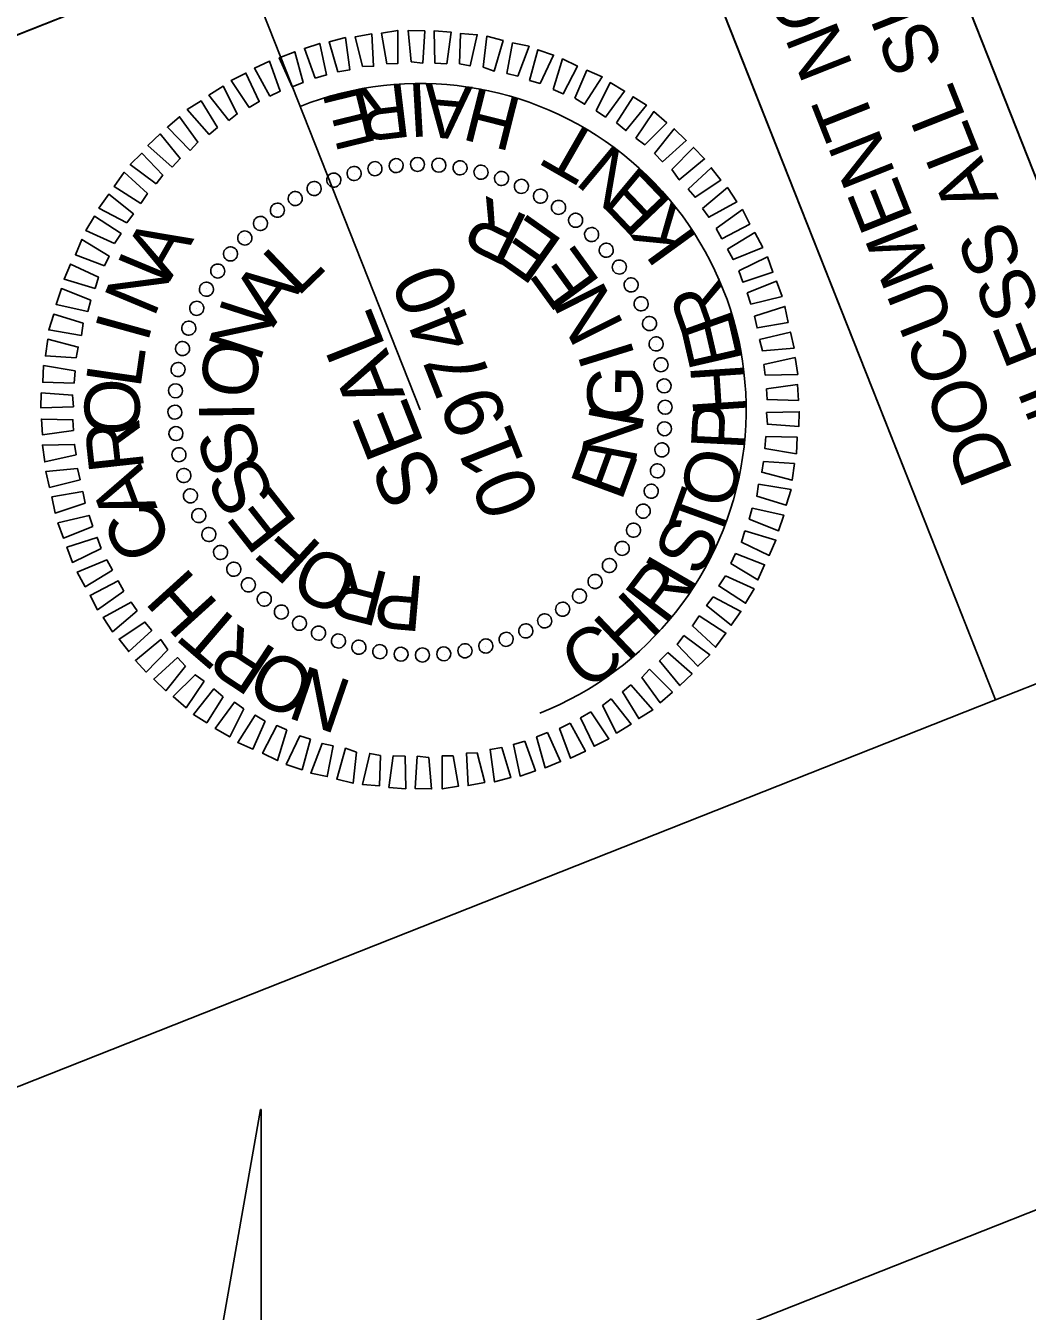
# Model space of a CAD drawing. Extents: x 1250120 to 1251758, y 748130 to 750098.
# Drawn here: x 1250261.4 to 1250363.9, y 749494.4 to 749625.9 of the extents above; entities that cross this region are included whole.
import ezdxf

# ---------------------------------------------------------------- set-up
doc = ezdxf.new("R2010")
doc.units = 0
for name, color, linetype in [('Prop North Arrow for Plan Sheets CELL', 7, 'Continuous'), ('Scratch_Level_0', 7, 'Continuous'), ('Scratch_Level_1', 7, 'Continuous'), ('Sheet Layout Plan Border', 7, 'Continuous'), ('Sheet Plan And Profile CELL', 7, 'Continuous'), ('Sheet Professional Seal CELL', 7, 'Continuous'), ('Sheet Sticker Exception Certification CELL', 7, 'Continuous')]:
    doc.layers.add(name, color=color, linetype=linetype)

msp = doc.modelspace()

# ---------------------------------------------------------------- linework, layer by layer
at = {"layer": 'Prop North Arrow for Plan Sheets CELL'}
for p, q in [((1250277.24, 749468.71), (1250285.44, 749515.06)), ((1250285.49, 749515.06), (1250285.44, 749515.06)), ((1250285.49, 749515.06), (1250285.44, 749515.06)), ((1250285.49, 749515.06), (1250285.49, 749467.26))]:
    msp.add_line(p, q, dxfattribs=at)
at = {"layer": 'Scratch_Level_0'}
msp.add_lwpolyline([(1250308.89, 749751.61), (1250344.17, 749765.56), (1250417.72, 749579.54), (1250382.44, 749565.59)], close=True, dxfattribs=at)
msp.add_arc((1250301.74, 749586.63), 33.36, 291.5743, 111.5743, dxfattribs=at)
at = {"layer": 'Scratch_Level_1'}
for q in [(1250206.96, 749826.33), (1250301.74, 749586.63)]:
    msp.add_line((1250301.74, 749586.63), q, dxfattribs=at)
at = {"layer": 'Sheet Layout Plan Border'}
msp.add_lwpolyline([(1251145.64, 748523.25), (1250727.17, 748357.78), (1250285.93, 749473.66), (1250436.11, 749533.04), (1250362.55, 749719.08), (1250630.85, 749825.16)], close=True, dxfattribs=at)
at = {"layer": 'Sheet Plan And Profile CELL'}
msp.add_line((1250219.18, 749608.62), (1250323.75, 749649.97), dxfattribs=at)
for points in [[(1250219.18, 749608.62), (1250182.41, 749701.61), (1250287.03, 749742.98), (1250323.8, 749649.99)], [(1250255.97, 749515.58), (1250219.18, 749608.62), (1250323.8, 749649.99), (1250360.59, 749556.95)]]:
    msp.add_lwpolyline(points, close=True, dxfattribs=at)
at = {"layer": 'Sheet Professional Seal CELL'}
for p, q in [((1250297.15, 749611.27), (1250297.15, 749611.27)), ((1250299.27, 749611.63), (1250299.27, 749611.63)), ((1250301.48, 749611.75), (1250301.48, 749611.75)), ((1250303.67, 749611.65), (1250303.67, 749611.65)), ((1250305.85, 749611.43), (1250305.85, 749611.43)), ((1250292.92, 749610.14), (1250292.92, 749610.14)), ((1250295.03, 749610.81), (1250295.03, 749610.81)), ((1250307.99, 749610.93), (1250307.99, 749610.93)), ((1250310.11, 749610.32), (1250310.11, 749610.32)), ((1250290.9, 749609.28), (1250290.9, 749609.28)), ((1250312.1, 749609.49), (1250312.1, 749609.49)), ((1250314.11, 749608.51), (1250314.11, 749608.51)), ((1250289.01, 749608.21), (1250289.01, 749608.21)), ((1250315.91, 749607.34), (1250315.91, 749607.34)), ((1250287.11, 749607.03), (1250287.11, 749607.03)), ((1250317.68, 749606), (1250317.68, 749606)), ((1250285.38, 749605.7), (1250285.38, 749605.7)), ((1250319.33, 749604.55), (1250319.33, 749604.55)), ((1250283.81, 749604.22), (1250283.81, 749604.22)), ((1250282.37, 749602.57), (1250282.37, 749602.57)), ((1250320.81, 749602.99), (1250320.81, 749602.99)), ((1250281.02, 749600.81), (1250281.02, 749600.81)), ((1250322.14, 749601.26), (1250322.14, 749601.26)), ((1250323.32, 749599.36), (1250323.32, 749599.36)), ((1250279.85, 749599), (1250279.85, 749599)), ((1250278.87, 749597), (1250278.87, 749597)), ((1250324.39, 749597.47), (1250324.39, 749597.47)), ((1250325.24, 749595.44), (1250325.24, 749595.44)), ((1250278.05, 749595.01), (1250278.05, 749595.01)), ((1250277.43, 749592.88), (1250277.43, 749592.88)), ((1250325.91, 749593.34), (1250325.91, 749593.34)), ((1250276.93, 749590.75), (1250276.93, 749590.75)), ((1250326.38, 749591.21), (1250326.38, 749591.21)), ((1250326.73, 749589.09), (1250326.73, 749589.09)), ((1250276.72, 749588.57), (1250276.72, 749588.57)), ((1250276.62, 749586.38), (1250276.62, 749586.38)), ((1250301.74, 749586.63), (1250301.74, 749586.63)), ((1250326.85, 749586.88), (1250326.85, 749586.88)), ((1250276.74, 749584.17), (1250276.74, 749584.17)), ((1250326.75, 749584.69), (1250326.75, 749584.69)), ((1250326.54, 749582.51), (1250326.54, 749582.51)), ((1250277.09, 749582.05), (1250277.09, 749582.05)), ((1250277.56, 749579.92), (1250277.56, 749579.92)), ((1250326.04, 749580.38), (1250326.04, 749580.38)), ((1250325.43, 749578.25), (1250325.43, 749578.25)), ((1250278.23, 749577.82), (1250278.23, 749577.82)), ((1250279.08, 749575.79), (1250279.08, 749575.79)), ((1250324.6, 749576.26), (1250324.6, 749576.26)), ((1250323.62, 749574.26), (1250323.62, 749574.26)), ((1250280.15, 749573.9), (1250280.15, 749573.9)), ((1250281.33, 749572), (1250281.33, 749572)), ((1250322.45, 749572.45), (1250322.45, 749572.45)), ((1250282.66, 749570.27), (1250282.66, 749570.27)), ((1250321.11, 749570.69), (1250321.11, 749570.69)), ((1250319.66, 749569.04), (1250319.66, 749569.04)), ((1250284.14, 749568.71), (1250284.14, 749568.71)), ((1250285.79, 749567.26), (1250285.79, 749567.26)), ((1250318.09, 749567.56), (1250318.09, 749567.56)), ((1250287.56, 749565.92), (1250287.56, 749565.92)), ((1250314.46, 749565.05), (1250314.46, 749565.05)), ((1250316.36, 749566.23), (1250316.36, 749566.23)), ((1250289.37, 749564.75), (1250289.37, 749564.75)), ((1250291.37, 749563.77), (1250291.37, 749563.77)), ((1250312.57, 749563.98), (1250312.57, 749563.98)), ((1250293.36, 749562.94), (1250293.36, 749562.94)), ((1250308.45, 749562.45), (1250308.45, 749562.45)), ((1250310.55, 749563.12), (1250310.55, 749563.12)), ((1250295.48, 749562.33), (1250295.48, 749562.33)), ((1250297.62, 749561.83), (1250297.62, 749561.83)), ((1250299.8, 749561.62), (1250299.8, 749561.62)), ((1250301.99, 749561.51), (1250301.99, 749561.51)), ((1250304.2, 749561.63), (1250304.2, 749561.63)), ((1250306.32, 749561.99), (1250306.32, 749561.99))]:
    msp.add_line(p, q, dxfattribs=at)
for points in [[(1250293.35, 749621.17), (1250292.45, 749624.25), (1250294.11, 749624.69), (1250294.56, 749621.37)], [(1250295.87, 749621.73), (1250295.1, 749624.76), (1250296.81, 749625.06), (1250296.99, 749621.75)], [(1250298.34, 749622.01), (1250297.8, 749625.13), (1250299.47, 749625.41), (1250299.46, 749622.02)], [(1250300.85, 749622.19), (1250300.54, 749625.41), (1250302.22, 749625.37), (1250302.02, 749622.07)], [(1250303.26, 749622.07), (1250303.19, 749625.38), (1250304.91, 749625.25), (1250304.47, 749622.01)], [(1250305.77, 749621.99), (1250305.88, 749625.1), (1250307.6, 749624.97), (1250306.87, 749621.78)], [(1250308.21, 749621.66), (1250308.57, 749624.82), (1250310.24, 749624.4), (1250309.34, 749621.25)], [(1250310.62, 749621), (1250311.21, 749624.14), (1250312.9, 749623.79), (1250311.74, 749620.75)], [(1250288.68, 749619.64), (1250287.35, 749622.61), (1250288.93, 749623.24), (1250289.8, 749620.08)], [(1250291.03, 749620.52), (1250289.92, 749623.57), (1250291.49, 749624.09), (1250292.18, 749620.86)], [(1250312.94, 749620.31), (1250313.79, 749623.44), (1250315.41, 749622.9), (1250314.03, 749619.99)], [(1250286.38, 749618.68), (1250284.81, 749621.55), (1250286.35, 749622.27), (1250287.45, 749619.21)], [(1250315.35, 749619.38), (1250316.32, 749622.5), (1250317.84, 749621.77), (1250316.39, 749618.93)], [(1250284.25, 749617.52), (1250282.41, 749620.28), (1250283.93, 749621.05), (1250285.3, 749618.14)], [(1250317.58, 749618.49), (1250318.82, 749621.34), (1250320.38, 749620.67), (1250318.58, 749617.86)], [(1250282.19, 749616.21), (1250280.15, 749618.79), (1250281.62, 749619.7), (1250283.05, 749616.88)], [(1250319.76, 749617.2), (1250321.2, 749620.08), (1250322.67, 749619.21), (1250320.71, 749616.55)], [(1250280.18, 749614.77), (1250277.93, 749617.33), (1250279.35, 749618.21), (1250281.02, 749615.49)], [(1250321.85, 749615.98), (1250323.54, 749618.64), (1250324.9, 749617.78), (1250322.81, 749615.18)], [(1250278.24, 749613.15), (1250275.91, 749615.51), (1250277.15, 749616.59), (1250279.03, 749614)], [(1250323.82, 749614.4), (1250325.65, 749617.11), (1250326.97, 749615.96), (1250324.73, 749613.73)], [(1250325.73, 749612.84), (1250327.74, 749615.36), (1250328.97, 749614.17), (1250326.55, 749611.98)], [(1250276.38, 749611.45), (1250273.9, 749613.64), (1250275.15, 749614.83), (1250277.22, 749612.32)], [(1250274.75, 749609.73), (1250272.1, 749611.69), (1250273.3, 749612.86), (1250275.42, 749610.63)], [(1250327.51, 749611.18), (1250329.73, 749613.45), (1250330.84, 749612.28), (1250328.25, 749610.13)], [(1250329.16, 749609.19), (1250331.53, 749611.37), (1250332.51, 749610.09), (1250329.87, 749608.35)], [(1250273.18, 749607.71), (1250270.44, 749609.47), (1250271.49, 749610.91), (1250273.86, 749608.73)], [(1250271.76, 749605.75), (1250268.9, 749607.25), (1250269.9, 749608.67), (1250272.42, 749606.65)], [(1250330.65, 749607.2), (1250333.19, 749609.34), (1250334.14, 749607.88), (1250331.27, 749606.32)], [(1250332.04, 749605.17), (1250334.72, 749607.09), (1250335.47, 749605.61), (1250332.62, 749604.11)], [(1250270.49, 749603.63), (1250267.56, 749604.95), (1250268.43, 749606.42), (1250271.17, 749604.65)], [(1250333.2, 749603.05), (1250335.98, 749604.74), (1250336.79, 749603.23), (1250333.78, 749601.99)], [(1250269.46, 749601.34), (1250266.49, 749602.48), (1250267.16, 749604.04), (1250269.93, 749602.34)], [(1250334.35, 749600.82), (1250337.28, 749602.25), (1250337.84, 749600.69), (1250334.75, 749599.68)], [(1250268.5, 749599.03), (1250265.33, 749599.98), (1250266, 749601.53), (1250268.85, 749600.19)], [(1250335.19, 749598.57), (1250338.21, 749599.76), (1250338.77, 749598.21), (1250335.58, 749597.43)], [(1250267.76, 749596.69), (1250264.52, 749597.4), (1250265.06, 749599.01), (1250268.06, 749597.83)], [(1250335.97, 749596.19), (1250339.07, 749597.2), (1250339.39, 749595.55), (1250336.22, 749595)], [(1250267.11, 749594.23), (1250263.77, 749594.79), (1250264.27, 749596.39), (1250267.27, 749595.48)], [(1250336.48, 749593.81), (1250339.62, 749594.57), (1250340, 749592.94), (1250336.78, 749592.64)], [(1250266.58, 749591.92), (1250263.43, 749592.13), (1250263.67, 749593.84), (1250266.78, 749593.03)], [(1250336.91, 749591.24), (1250340.11, 749591.97), (1250340.37, 749590.24), (1250337.06, 749590.17)], [(1250266.35, 749589.36), (1250263.15, 749589.44), (1250263.23, 749591.14), (1250266.46, 749590.59)], [(1250337.18, 749588.76), (1250340.34, 749589.21), (1250340.45, 749587.58), (1250337.24, 749587.66)], [(1250266.3, 749586.92), (1250262.94, 749586.83), (1250262.99, 749588.35), (1250266.2, 749588.12)], [(1250337.17, 749586.34), (1250340.53, 749586.43), (1250340.48, 749584.91), (1250337.27, 749585.14)], [(1250266.29, 749584.5), (1250263.13, 749584.05), (1250263.02, 749585.68), (1250266.23, 749585.6)], [(1250337.12, 749583.9), (1250340.32, 749583.82), (1250340.24, 749582.12), (1250337.01, 749582.67)], [(1250266.56, 749582.02), (1250263.36, 749581.29), (1250263.11, 749583.02), (1250266.41, 749583.09)], [(1250336.89, 749581.34), (1250340.04, 749581.13), (1250339.8, 749579.42), (1250336.69, 749580.23)], [(1250266.99, 749579.45), (1250263.85, 749578.69), (1250263.48, 749580.32), (1250266.69, 749580.62)], [(1250267.5, 749577.07), (1250264.41, 749576.06), (1250264.08, 749577.71), (1250267.25, 749578.26)], [(1250336.36, 749579.03), (1250339.7, 749578.47), (1250339.2, 749576.87), (1250336.2, 749577.78)], [(1250268.28, 749574.69), (1250265.26, 749573.5), (1250264.7, 749575.05), (1250267.89, 749575.83)], [(1250335.72, 749576.57), (1250338.95, 749575.86), (1250338.41, 749574.25), (1250335.41, 749575.43)], [(1250334.97, 749574.23), (1250338.14, 749573.28), (1250337.47, 749571.73), (1250334.62, 749573.07)], [(1250269.12, 749572.44), (1250266.19, 749571.01), (1250265.63, 749572.57), (1250268.72, 749573.58)], [(1250334.01, 749571.92), (1250336.98, 749570.78), (1250336.31, 749569.22), (1250333.54, 749570.92)], [(1250270.27, 749570.21), (1250267.5, 749568.52), (1250266.68, 749570.03), (1250269.69, 749571.27)], [(1250271.43, 749568.09), (1250268.75, 749566.17), (1250268, 749567.65), (1250270.85, 749569.15)], [(1250332.98, 749569.63), (1250335.91, 749568.31), (1250335.05, 749566.84), (1250332.3, 749568.61)], [(1250272.82, 749566.06), (1250270.28, 749563.92), (1250269.33, 749565.38), (1250272.21, 749566.94)], [(1250331.71, 749567.51), (1250334.57, 749566.01), (1250333.57, 749564.59), (1250331.05, 749566.61)], [(1250330.29, 749565.55), (1250333.03, 749563.79), (1250331.98, 749562.35), (1250329.61, 749564.53)], [(1250274.31, 749564.07), (1250271.94, 749561.89), (1250270.96, 749563.17), (1250273.6, 749564.91)], [(1250275.96, 749562.08), (1250273.74, 749559.81), (1250272.63, 749560.98), (1250275.22, 749563.13)], [(1250328.72, 749563.53), (1250331.38, 749561.57), (1250330.17, 749560.4), (1250328.06, 749562.63)], [(1250277.74, 749560.42), (1250275.73, 749557.9), (1250274.51, 749559.09), (1250276.92, 749561.28)], [(1250327.09, 749561.81), (1250329.57, 749559.62), (1250328.32, 749558.43), (1250326.25, 749560.94)], [(1250325.23, 749560.11), (1250327.56, 749557.75), (1250326.32, 749556.67), (1250324.44, 749559.26)], [(1250279.65, 749558.86), (1250277.82, 749556.15), (1250276.5, 749557.3), (1250278.74, 749559.53)], [(1250323.29, 749558.49), (1250325.54, 749555.93), (1250324.12, 749555.05), (1250322.45, 749557.77)], [(1250281.62, 749557.28), (1250279.93, 749554.62), (1250278.57, 749555.48), (1250280.66, 749558.08)], [(1250283.71, 749556.06), (1250282.27, 749553.18), (1250280.8, 749554.05), (1250282.76, 749556.71)], [(1250321.28, 749557.05), (1250323.33, 749554.47), (1250321.85, 749553.56), (1250320.42, 749556.38)], [(1250285.89, 749554.77), (1250284.65, 749551.92), (1250283.1, 749552.59), (1250284.89, 749555.4)], [(1250317.1, 749554.58), (1250318.66, 749551.71), (1250317.12, 749550.99), (1250316.02, 749554.05)], [(1250319.22, 749555.74), (1250321.06, 749552.98), (1250319.54, 749552.21), (1250318.17, 749555.12)], [(1250288.12, 749553.88), (1250287.16, 749550.76), (1250285.63, 749551.5), (1250287.09, 749554.33)], [(1250290.53, 749552.95), (1250289.68, 749549.82), (1250288.06, 749550.36), (1250289.44, 749553.27)], [(1250314.79, 749553.62), (1250316.12, 749550.65), (1250314.54, 749550.02), (1250313.67, 749553.18)], [(1250292.85, 749552.26), (1250292.26, 749549.12), (1250290.57, 749549.47), (1250291.73, 749552.51)], [(1250295.26, 749551.6), (1250294.9, 749548.44), (1250293.23, 749548.86), (1250294.13, 749552.01)], [(1250310.12, 749552.09), (1250311.02, 749549.01), (1250309.37, 749548.57), (1250308.91, 749551.89)], [(1250312.45, 749552.74), (1250313.55, 749549.69), (1250311.98, 749549.17), (1250311.29, 749552.4)], [(1250297.71, 749551.27), (1250297.59, 749548.16), (1250295.87, 749548.29), (1250296.6, 749551.48)], [(1250300.21, 749551.19), (1250300.28, 749547.88), (1250298.56, 749548.01), (1250299, 749551.25)], [(1250302.63, 749551.07), (1250302.93, 749547.85), (1250301.25, 749547.89), (1250301.45, 749551.19)], [(1250305.13, 749551.25), (1250305.67, 749548.13), (1250304.01, 749547.85), (1250304.01, 749551.24)], [(1250307.6, 749551.53), (1250308.37, 749548.5), (1250306.66, 749548.2), (1250306.48, 749551.51)]]:
    msp.add_lwpolyline(points, close=True, dxfattribs=at)
for centre, major_axis in [((1250299.3, 749611.59), (-0.07, 0.717)), ((1250301.48, 749611.71), (-0.007, 0.72)), ((1250303.67, 749611.64), (0.056, 0.718)), ((1250295, 749610.79), (-0.193, 0.694)), ((1250297.13, 749611.28), (-0.132, 0.708)), ((1250305.84, 749611.37), (0.118, 0.71)), ((1250307.98, 749610.92), (0.179, 0.697)), ((1250310.08, 749610.28), (0.239, 0.679)), ((1250290.91, 749609.25), (-0.311, 0.649)), ((1250292.92, 749610.11), (-0.253, 0.674)), ((1250312.11, 749609.47), (0.298, 0.656)), ((1250288.98, 749608.22), (-0.366, 0.62)), ((1250314.06, 749608.47), (0.354, 0.627)), ((1250287.15, 749607.03), (-0.419, 0.586)), ((1250315.91, 749607.32), (0.407, 0.594)), ((1250285.42, 749605.68), (-0.468, 0.547)), ((1250317.66, 749606), (0.457, 0.556)), ((1250283.82, 749604.19), (-0.514, 0.504)), ((1250319.29, 749604.54), (0.504, 0.514)), ((1250282.36, 749602.56), (-0.556, 0.457)), ((1250320.79, 749602.94), (0.547, 0.468)), ((1250322.13, 749601.22), (0.586, 0.419)), ((1250281.05, 749600.81), (-0.594, 0.407)), ((1250279.89, 749598.95), (-0.627, 0.354)), ((1250323.33, 749599.39), (0.62, 0.366)), ((1250324.36, 749597.46), (0.649, 0.311)), ((1250278.9, 749597), (-0.656, 0.298)), ((1250278.08, 749594.97), (-0.679, 0.239)), ((1250325.22, 749595.44), (0.674, 0.253)), ((1250325.89, 749593.36), (0.694, 0.193)), ((1250277.45, 749592.88), (-0.697, 0.179)), ((1250276.99, 749590.74), (-0.71, 0.118)), ((1250326.39, 749591.23), (0.708, 0.132)), ((1250276.73, 749588.57), (-0.718, 0.056)), ((1250326.7, 749589.07), (0.717, 0.07)), ((1250326.81, 749586.88), (0.72, 0.007)), ((1250276.66, 749586.38), (-0.72, -0.007)), ((1250276.77, 749584.19), (-0.717, -0.07)), ((1250326.74, 749584.69), (0.718, -0.056)), ((1250277.08, 749582.03), (-0.708, -0.132)), ((1250326.48, 749582.52), (0.71, -0.118)), ((1250326.02, 749580.38), (0.697, -0.179)), ((1250277.58, 749579.9), (-0.694, -0.193)), ((1250278.26, 749577.82), (-0.674, -0.253)), ((1250325.39, 749578.29), (0.679, -0.239)), ((1250324.57, 749576.26), (0.656, -0.298)), ((1250279.11, 749575.8), (-0.649, -0.311)), ((1250280.14, 749573.87), (-0.62, -0.366)), ((1250323.58, 749574.31), (0.627, -0.354)), ((1250322.42, 749572.45), (0.594, -0.407)), ((1250281.34, 749572.04), (-0.586, -0.419)), ((1250282.69, 749570.32), (-0.547, -0.468)), ((1250321.11, 749570.7), (0.556, -0.457)), ((1250284.18, 749568.72), (-0.504, -0.514)), ((1250319.65, 749569.07), (0.514, -0.504)), ((1250285.81, 749567.26), (-0.457, -0.556)), ((1250318.05, 749567.58), (0.468, -0.547)), ((1250287.56, 749565.94), (-0.407, -0.594)), ((1250316.33, 749566.23), (0.419, -0.586)), ((1250289.41, 749564.79), (-0.354, -0.627)), ((1250314.49, 749565.04), (0.366, -0.62)), ((1250291.36, 749563.79), (-0.298, -0.656)), ((1250293.39, 749562.98), (-0.239, -0.679)), ((1250310.55, 749563.15), (0.253, -0.674)), ((1250312.56, 749564.01), (0.311, -0.649)), ((1250295.49, 749562.34), (-0.179, -0.697)), ((1250297.63, 749561.89), (-0.118, -0.71)), ((1250299.8, 749561.62), (-0.056, -0.718)), ((1250304.17, 749561.67), (0.07, -0.717)), ((1250306.34, 749561.98), (0.132, -0.708)), ((1250308.47, 749562.47), (0.193, -0.694)), ((1250301.99, 749561.55), (0.007, -0.72))]:
    msp.add_ellipse(centre, major_axis=major_axis, ratio=0.999708, dxfattribs=at)
at = {"layer": 'Sheet Sticker Exception Certification CELL'}
for p, q in [((1250308.89, 749751.61), (1250382.44, 749565.59)), ((1250360.59, 749556.95), (1250287.03, 749742.97)), ((1250382.44, 749565.59), (1250360.59, 749556.95))]:
    msp.add_line(p, q, dxfattribs=at)

# ---------------------------------------------------------------- texts
at = {"layer": 'Sheet Professional Seal CELL'}
for s, height, rotation, p in [('E', 5.5, 193.7569, (1250296.31, 749619.65)), ('R', 5.5, 186.8304, (1250300.33, 749620.06)), ('I', 5.5, 183.31, (1250302.39, 749620.09)), ('A', 5.5, 175.1242, (1250307.15, 749619.65)), ('H', 5.5, 165.8794, (1250312.38, 749618.36)), ('T', 5.5, 150.1375, (1250320.59, 749614.28)), ('N', 5.5, 140.2057, (1250325.07, 749610.61)), ('E', 5.5, 133.6228, (1250327.67, 749607.78)), ('R', 5.64, 154.0558, (1250313.06, 749606.27)), ('K', 5.5, 125.9522, (1250330.26, 749604.13)), ('E', 5.64, 144.6984, (1250316.55, 749603.83)), ('A', 5.64, 60.1915, (1250276.17, 749599.75)), ('E', 5.64, 125.9861, (1250320.31, 749599.62)), ('N', 5.64, 67.3933, (1250274.51, 749595.92)), ('L', 5.64, 43.9752, (1250289.2, 749598.07)), ('A', 5.64, 53.3346, (1250286.71, 749594.99)), ('019740', 5.998, 111.5743, (1250314.1, 749577.14)), ('N', 5.64, 116.6307, (1250322.69, 749595.24)), ('R', 5.5, 109.5806, (1250334.04, 749595.38)), ('N', 5.64, 72.051, (1250285.34, 749591.38)), ('SEAL', 5.998, 111.5743, (1250304.18, 749578.14)), ('I', 5.64, 74.5945, (1250273.86, 749593.35)), ('E', 5.5, 102.9976, (1250334.83, 749591.62)), ('L', 5.64, 81.7952, (1250273.12, 749588.7)), ('O', 5.64, 81.4078, (1250284.71, 749587.53)), ('I', 5.64, 107.2755, (1250323.78, 749592.07)), ('G', 5.64, 88.5646, (1250324.42, 749585.28)), ('H', 5.5, 93.7528, (1250335.2, 749586.24)), ('O', 5.64, 88.9955, (1250273.02, 749583.93)), ('I', 5.64, 90.764, (1250284.8, 749585.42)), ('N', 5.64, 79.2083, (1250323.73, 749580.92)), ('P', 5.5, 87.1698, (1250334.93, 749582.4)), ('R', 5.64, 96.1954, (1250273.55, 749580.54)), ('S', 5.64, 109.4747, (1250285.73, 749581.16)), ('E', 5.64, 69.8512, (1250322.32, 749577.13)), ('O', 5.5, 76.4653, (1250333.57, 749576.31)), ('A', 5.64, 110.5947, (1250274.91, 749576.56)), ('S', 5.64, 118.83, (1250287.1, 749577.83)), ('E', 5.64, 128.1854, (1250289.34, 749575.01)), ('T', 5.5, 70.1685, (1250332.24, 749572.88)), ('C', 5.64, 117.7942, (1250276.64, 749573)), ('S', 5.5, 63.3852, (1250330.41, 749569.37)), ('F', 5.64, 137.5414, (1250291.91, 749572.58)), ('O', 5.64, 156.2556, (1250295.87, 749570.6)), ('I', 5.5, 59.8647, (1250329.29, 749567.65)), ('H', 5.64, 132.1938, (1250281.29, 749566.67)), ('R', 5.64, 165.614, (1250298.79, 749569.87)), ('R', 5.5, 52.9383, (1250326.8, 749564.46)), ('P', 5.64, 174.9732, (1250302.36, 749569.56)), ('H', 5.5, 43.6935, (1250322.92, 749560.72)), ('T', 5.64, 139.3941, (1250284.02, 749564.25)), ('R', 5.64, 146.5949, (1250287.32, 749561.9)), ('C', 5.5, 34.8208, (1250318.67, 749557.77)), ('O', 5.64, 153.7961, (1250291.47, 749559.83)), ('N', 5.64, 160.9978, (1250295.01, 749558.76))]:
    msp.add_text(s, height=height, rotation=rotation, dxfattribs=at).set_placement(p)
at = {"layer": 'Sheet Sticker Exception Certification CELL'}
for s, p in [('UNLESS ALL SIGNATURES COMPLETED', (1250372.51, 749578.87)), ('DOCUMENT NOT CONSIDERED FINAL', (1250362.46, 749580.35))]:
    msp.add_text(s, height=5.5, rotation=111.5743, dxfattribs=at).set_placement(p)

doc.saveas('drawing.dxf')
